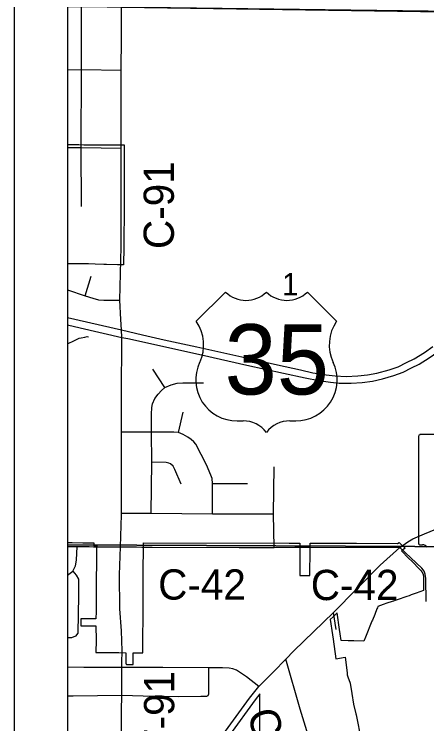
# Model space of a CAD drawing. Extents: x 0 to 34, y 0 to 22.
# Drawn here: x 2 to 2.775, y 16.149 to 17.481 of the extents above; entities that cross this region are included whole.
import ezdxf

# ---------------------------------------------------------------- set-up
doc = ezdxf.new("R2010")
doc.units = 0
for name, color, linetype in [('Default', 7, 'Continuous'), ('GM_X_City_Street', 7, 'Continuous'), ('GM_X_County_Road', 7, 'Continuous'), ('GM_X_County_Road_Text', 7, 'Continuous'), ('GM_X_Minor_River', 7, 'Continuous'), ('GM_X_Section_Text', 7, 'Continuous'), ('GM_X_State_Route', 7, 'Continuous'), ('GM_X_State_Shield', 7, 'Continuous'), ('GM_X_Township_Road', 7, 'Continuous'), ('GM_X_Township_Road_Text', 7, 'Continuous'), ('GM_X_US_Location', 7, 'Continuous'), ('GM_X_US_Route', 7, 'Continuous'), ('GM_X_US_Shield', 7, 'Continuous'), ('SH_Data', 7, 'Continuous')]:
    doc.layers.add(name, color=color, linetype=linetype)

msp = doc.modelspace()

# ---------------------------------------------------------------- linework, layer by layer
at = {"layer": 'Default'}
for points in [[(2.1, 17.4954), (2.1, 16.4848), (3.0135, 16.4807), (3.0196, 17.4831)], [(2.1, 16.4848), (2.1, 15.4427), (3.0163, 15.4353), (3.0168, 15.4789), (3.0135, 16.4807)]]:
    msp.add_lwpolyline(points, close=True, dxfattribs=at)
at = {"layer": 'GM_X_City_Street'}
for p, q in [((2.1335, 16.9523), (2.1447, 16.9889)), ((2.283, 16.78), (2.2602, 16.8145)), ((2.3084, 16.6957), (2.3175, 16.7341)), ((2.3722, 16.5999), (2.4381, 16.5998)), ((2.6045, 16.3261), (2.5999, 16.3579))]:
    msp.add_line(p, q, dxfattribs=at)
for points in [[(2.126, 17.2305), (2.1263, 17.3766), (2.1264, 17.4939)], [(2.1, 17.3765), (2.1263, 17.3766), (2.2007, 17.3758)], [(2.1, 16.9636), (2.1335, 16.9523), (2.148, 16.9475), (2.1585, 16.9449), (2.1682, 16.9438), (2.1982, 16.9438)], [(2.2574, 16.5444), (2.2585, 16.6399), (2.2579, 16.6963), (2.2576, 16.7301), (2.2584, 16.7424), (2.2598, 16.7492), (2.2642, 16.7593), (2.2704, 16.7675), (2.2767, 16.7744), (2.283, 16.78), (2.295, 16.7851), (2.3063, 16.7882), (2.317, 16.7888), (2.3552, 16.7886)], [(2.3722, 16.5433), (2.3722, 16.5999), (2.3717, 16.6094), (2.3694, 16.6156), (2.361, 16.6352), (2.3414, 16.6739), (2.3375, 16.6784), (2.3325, 16.6828), (2.3263, 16.6868), (2.3173, 16.6918), (2.3084, 16.6957), (2.3, 16.6963), (2.2579, 16.6963), (2.2017, 16.6961)], [(2.3138, 16.5988), (2.3017, 16.626), (2.2984, 16.6325), (2.2938, 16.6366), (2.2905, 16.638), (2.2856, 16.6396), (2.2585, 16.6399)], [(2.4882, 16.48), (2.4871, 16.5427), (2.4882, 16.6313)], [(2.2015, 16.5444), (2.2574, 16.5444), (2.3722, 16.5433), (2.4871, 16.5427)], [(2.7739, 16.3787), (2.7728, 16.4216), (2.772, 16.4295), (2.7702, 16.4351), (2.7657, 16.4411), (2.7241, 16.4797)]]:
    msp.add_lwpolyline(points, dxfattribs=at)
at = {"layer": 'GM_X_County_Road'}
for p, q in [((2.1999, 16.4809), (2.201, 16.5209)), ((2.556, 16.4802), (2.7241, 16.4797))]:
    msp.add_line(p, q, dxfattribs=at)
for points in [[(2.2008, 17.3809), (2.2014, 17.4312), (2.2017, 17.4929), (2.2017, 17.5019)], [(2.2006, 17.2295), (2.2011, 17.2643), (2.2007, 17.3758), (2.2008, 17.3809)], [(2.2011, 17.0443), (2.2012, 17.0502), (2.2006, 17.2295)], [(2.2005, 16.9078), (2.1982, 16.9438), (2.2011, 17.0443)], [(2.202, 16.8638), (2.202, 16.8739), (2.2017, 16.8884), (2.2005, 16.9078)], [(2.2016, 16.5816), (2.2017, 16.6961), (2.2017, 16.7751), (2.202, 16.8638)], [(2.201, 16.5209), (2.2015, 16.5409), (2.2015, 16.5444), (2.2016, 16.5816)], [(2.1, 16.4815), (2.1181, 16.4815), (2.121, 16.4815), (2.1285, 16.4814)], [(2.1285, 16.4814), (2.1317, 16.4814), (2.1406, 16.4814), (2.1489, 16.4813)], [(2.1489, 16.4813), (2.1549, 16.4813), (2.159, 16.4812)], [(2.159, 16.4812), (2.1999, 16.4809), (2.2295, 16.4808), (2.2394, 16.4807)], [(2.2394, 16.4807), (2.2591, 16.4805), (2.4222, 16.4797), (2.4777, 16.4799), (2.4863, 16.48)], [(2.4863, 16.48), (2.4882, 16.48), (2.5273, 16.4802), (2.5362, 16.4802)], [(2.5362, 16.4802), (2.5372, 16.4802), (2.5471, 16.4802), (2.556, 16.4802)], [(2.5732, 16.0595), (2.5729, 16.0605), (2.5369, 16.1764), (2.5102, 16.27)]]:
    msp.add_lwpolyline(points, dxfattribs=at)
at = {"layer": 'GM_X_Minor_River'}
msp.add_lwpolyline([(2.1, 16.8618), (2.1038, 16.8637), (2.1096, 16.8666), (2.122, 16.8724), (2.1258, 16.8735), (2.1327, 16.8748), (2.1369, 16.8755), (2.1396, 16.8754)], dxfattribs=at)
at = {"layer": 'GM_X_State_Route'}
for points in [[(2.1, 17.7063), (2.1, 17.2361), (2.1079, 17.236), (2.1211, 17.2359), (2.1306, 17.2358), (2.1614, 17.2356), (2.1644, 17.2355), (2.1952, 17.2353), (2.2066, 17.2352), (2.2063, 17.1184), (2.2063, 17.1106), (2.2062, 17.0554), (2.2062, 17.0517), (2.2061, 17.0489), (2.206, 17.0432), (2.2055, 17.0106), (2.2055, 17.0104), (2.196, 17.0106), (2.194, 17.0106), (2.1736, 17.0111), (2.1686, 17.0112), (2.1522, 17.0116), (2.1396, 17.0119), (2.1252, 17.0122), (2.1204, 17.0123), (2.1156, 17.0123), (2.1017, 17.0124), (2.1, 17.0124), (2.1, 16.4889), (2.1088, 16.4889), (2.1287, 16.4888), (2.1494, 16.4888), (2.1494, 16.4831), (2.1549, 16.4831), (2.1548, 16.4775), (2.1548, 16.4737), (2.1544, 16.4411), (2.1541, 16.4292), (2.1539, 16.4238), (2.1539, 16.4222), (2.154, 16.4125), (2.1539, 16.3992), (2.1538, 16.3859), (2.1537, 16.3727), (2.1537, 16.3594), (2.1536, 16.3462), (2.1252, 16.3461), (2.1251, 16.3328), (2.1535, 16.3329), (2.1539, 16.3056), (2.1533, 16.2829), (2.1579, 16.2828), (2.17, 16.2827), (2.1821, 16.2826), (2.1963, 16.2825), (2.2095, 16.2824), (2.2095, 16.2629), (2.2095, 16.2628), (2.2095, 16.2627), (2.2095, 16.2625), (2.2095, 16.2623), (2.2095, 16.2623), (2.2096, 16.2622), (2.2096, 16.262), (2.2097, 16.2619), (2.2097, 16.2618), (2.2098, 16.2617), (2.2098, 16.2616), (2.2099, 16.2615), (2.21, 16.2613), (2.2101, 16.2612), (2.2102, 16.2611), (2.2103, 16.261), (2.2104, 16.2609), (2.2105, 16.2608), (2.2106, 16.2607), (2.2108, 16.2606), (2.2109, 16.2605), (2.211, 16.2604), (2.2111, 16.2604), (2.2112, 16.2604), (2.2114, 16.2603), (2.2114, 16.2603), (2.2115, 16.2603), (2.2117, 16.2602), (2.2119, 16.2602), (2.212, 16.2602), (2.2121, 16.2602), (2.2123, 16.2602), (2.2236, 16.2601), (2.2237, 16.2823), (2.2359, 16.2823), (2.2413, 16.2823), (2.2416, 16.3012), (2.2418, 16.3201), (2.242, 16.3391), (2.2422, 16.3502), (2.2422, 16.358), (2.2421, 16.3769), (2.2422, 16.3959), (2.2424, 16.4167), (2.2425, 16.4377), (2.2428, 16.4771), (2.2429, 16.4886), (2.5162, 16.4882), (2.5238, 16.4882), (2.5367, 16.4881), (2.5366, 16.4758), (2.5362, 16.4271), (2.547, 16.4272), (2.5555, 16.4273), (2.556, 16.4758), (2.5561, 16.4881), (2.5754, 16.4881), (2.5787, 16.488), (2.636, 16.4878), (2.6431, 16.4877), (2.7198, 16.4871), (2.7231, 16.4895), (2.734, 16.4786), (2.7271, 16.4734), (2.7404, 16.4601), (2.7472, 16.4533), (2.7611, 16.4394), (2.763, 16.4375), (2.7634, 16.4371), (2.7636, 16.4368), (2.7639, 16.4365), (2.7641, 16.4362), (2.7643, 16.4359), (2.7646, 16.4356), (2.7648, 16.4353), (2.765, 16.435), (2.7652, 16.4347), (2.7655, 16.4343), (2.7657, 16.434), (2.7659, 16.4337), (2.7661, 16.4333), (2.7662, 16.433), (2.7664, 16.4327), (2.7666, 16.4323), (2.7668, 16.432), (2.7669, 16.4316), (2.7671, 16.4313), (2.7672, 16.4309), (2.7674, 16.4306), (2.7675, 16.4302), (2.7677, 16.4298), (2.7678, 16.4295), (2.7679, 16.4291), (2.768, 16.4287), (2.7681, 16.4284), (2.7682, 16.428), (2.7683, 16.4276), (2.7684, 16.4273), (2.7685, 16.4269), (2.7686, 16.4265), (2.7686, 16.4261), (2.7687, 16.4257), (2.7687, 16.4254), (2.7688, 16.425), (2.7688, 16.4246), (2.7689, 16.4242), (2.7689, 16.4241), (2.7689, 16.4238), (2.7689, 16.4234), (2.7689, 16.4231), (2.7689, 16.4227), (2.7689, 16.4223), (2.7689, 16.4219), (2.7689, 16.4215), (2.7689, 16.4211), (2.7689, 16.4161), (2.7689, 16.4065), (2.7689, 16.3989), (2.7549, 16.394), (2.7456, 16.3908), (2.7441, 16.3903), (2.7428, 16.3899), (2.7415, 16.3894), (2.7372, 16.3879), (2.7195, 16.3818), (2.7153, 16.3804), (2.7123, 16.3794), (2.7116, 16.3791), (2.71, 16.3786), (2.7078, 16.3778), (2.7018, 16.3757), (2.6998, 16.3751), (2.6928, 16.3726), (2.6831, 16.3693), (2.682, 16.3666), (2.6812, 16.3646), (2.677, 16.3542), (2.6727, 16.3437), (2.6718, 16.3415), (2.6597, 16.3118), (2.6566, 16.3043), (2.6379, 16.3047), (2.6269, 16.3049), (2.6139, 16.3053), (2.6123, 16.3177), (2.6122, 16.3179), (2.6111, 16.3259), (2.6066, 16.3574), (2.599, 16.3499), (2.5936, 16.3446), (2.5977, 16.3156), (2.5988, 16.3078), (2.6039, 16.2709), (2.6214, 16.2739), (2.625, 16.2445), (2.6255, 16.2406), (2.6268, 16.237), (2.6308, 16.2254), (2.634, 16.2057), (2.6375, 16.1856), (2.6415, 16.1674), (2.6419, 16.1655), (2.6452, 16.1499), (2.6486, 16.1341)], [(2.7241, 16.4797), (2.7391, 16.4902), (2.7488, 16.4958), (2.7704, 16.5056), (2.8022, 16.5188), (2.8401, 16.5344), (2.8948, 16.5568), (2.9692, 16.5869), (2.9718, 16.588)], [(2.5102, 16.27), (2.525, 16.2858), (2.5999, 16.3579), (2.6873, 16.4465), (2.7241, 16.4797)], [(2.3334, 16.0479), (2.3508, 16.0723), (2.3775, 16.1087), (2.3919, 16.1283), (2.4166, 16.1625), (2.4419, 16.1972), (2.4592, 16.2187), (2.4869, 16.2465), (2.5102, 16.27)], [(2.4612, 16.1256), (2.4614, 16.1634), (2.4615, 16.1793), (2.4616, 16.2052), (2.4523, 16.1939), (2.4043, 16.1276)]]:
    msp.add_lwpolyline(points, dxfattribs=at)
at = {"layer": 'GM_X_State_Shield'}
for p, q in [((2.7592, 16.6881), (2.7592, 16.488)), ((2.839, 16.6916), (2.7618, 16.6916))]:
    msp.add_line(p, q, dxfattribs=at)
for centre, radius, start, end in [((2.7622, 16.6885), 0.00305, 98.1301, 188.1301), ((2.7622, 16.4876), 0.00308, 171.9584, 258.3066), ((2.7627, 16.508), 0.0235, 267.339, 280.6039), ((2.7675, 16.4764), 0.00848, 29.7484, 93.2717)]:
    msp.add_arc(centre, radius, start, end, dxfattribs=at)
at = {"layer": 'GM_X_Township_Road'}
for p, q in [((2.1265, 17.1196), (2.126, 17.2305)), ((2.1076, 16.3102), (2.1, 16.3102))]:
    msp.add_line(p, q, dxfattribs=at)
for points in [[(3.0233, 15.5768), (3.0198, 16.3586), (3.018, 16.4163), (3.0163, 16.6061), (3.0141, 16.8752), (3.0141, 16.8793), (3.0149, 17.0299), (3.0151, 17.0528), (3.0151, 17.0635), (3.0153, 17.0702), (3.0204, 17.2302), (3.021, 17.2383), (3.0221, 17.3705), (3.0222, 17.3748), (3.0222, 17.4806), (3.0222, 17.4813), (2.2015, 17.4935), (2.1476, 17.4943), (2.1261, 17.4945), (2.1, 17.494), (2.1, 14.1)], [(2.1, 17.2305), (2.126, 17.2305), (2.2006, 17.2295)], [(2.1, 16.4277), (2.1102, 16.4356), (2.115, 16.4457), (2.1172, 16.4558), (2.1181, 16.4815)], [(2.203, 16.2857), (2.2017, 16.3232), (2.1982, 16.3648), (2.1978, 16.4286), (2.1999, 16.4809)], [(2.1102, 16.4356), (2.1165, 16.4276), (2.1208, 16.4204), (2.1208, 16.3896), (2.1194, 16.3191), (2.1153, 16.3131), (2.1076, 16.3102)], [(2.2023, 16.2649), (2.203, 16.2847), (2.203, 16.2857)], [(2.2039, 16.0584), (2.2024, 16.0713), (2.202, 16.0877), (2.202, 16.0967), (2.2013, 16.1452), (2.2018, 16.1738), (2.2021, 16.202), (2.2019, 16.2238), (2.2019, 16.2544), (2.2023, 16.2649)], [(2.4592, 16.2187), (2.4364, 16.2372), (2.427, 16.2435), (2.4173, 16.2495), (2.4104, 16.2522), (2.4035, 16.2533), (2.3909, 16.254), (2.3652, 16.254), (2.2791, 16.2547), (2.2019, 16.2544), (2.1306, 16.2546), (2.1, 16.2551)], [(2.3652, 16.254), (2.3649, 16.2117), (2.3646, 16.2046), (2.3637, 16.2014), (2.3609, 16.2001), (2.3503, 16.2004), (2.308, 16.1997), (2.2625, 16.2001), (2.2021, 16.202), (2.111, 16.2009), (2.1, 16.2009)]]:
    msp.add_lwpolyline(points, dxfattribs=at)
at = {"layer": 'GM_X_US_Route'}
for p, q in [((2.1, 16.9117), (2.2017, 16.8884)), ((2.1, 16.8974), (2.1242, 16.8918)), ((2.1242, 16.8918), (2.202, 16.8739))]:
    msp.add_line(p, q, dxfattribs=at)
for points in [[(2.202, 16.8739), (2.2133, 16.8718), (2.3519, 16.8412), (2.4371, 16.8223), (2.5059, 16.8068), (2.5465, 16.7983), (2.5722, 16.7932), (2.5937, 16.7899), (2.6104, 16.7884), (2.6327, 16.7884), (2.6536, 16.7897), (2.6727, 16.792), (2.6914, 16.7966), (2.7128, 16.8025), (2.7303, 16.8089), (2.7461, 16.8168), (2.7602, 16.8239), (2.7796, 16.8359), (2.7954, 16.8472), (2.8124, 16.8611), (2.8731, 16.9178), (2.906, 16.9486), (2.937, 16.9785)], [(2.2017, 16.8884), (2.2408, 16.879), (2.2819, 16.8698), (2.3431, 16.8566), (2.4276, 16.8374), (2.4944, 16.8226), (2.5374, 16.813), (2.5609, 16.8079), (2.5856, 16.804), (2.603, 16.8017), (2.6236, 16.8009), (2.6453, 16.8018), (2.6637, 16.8038), (2.6813, 16.8073), (2.7043, 16.8135), (2.7211, 16.8189), (2.7369, 16.8268), (2.7511, 16.8339), (2.7705, 16.8459), (2.7862, 16.8572)]]:
    msp.add_lwpolyline(points, dxfattribs=at)
at = {"layer": 'GM_X_US_Shield'}
for p, q in [((2.3968, 16.9592), (2.3419, 16.9043)), ((2.6055, 16.9043), (2.5506, 16.9592)), ((2.4188, 16.7175), (2.4297, 16.7175)), ((2.5176, 16.7175), (2.5286, 16.7175))]:
    msp.add_line(p, q, dxfattribs=at)
for centre, radius, start, end in [((2.4352, 16.9985), 0.0549, 225.573, 314.427), ((2.5121, 16.9985), 0.0549, 225.573, 314.427), ((2.2789, 16.8602), 0.0769, 334.5471, 35.0009), ((2.6685, 16.8602), 0.0769, 144.9991, 205.4529), ((2.4179, 16.7944), 0.0769, 154.8319, 270.6383), ((2.5295, 16.7944), 0.0769, 269.3617, 25.1681), ((2.4297, 16.6626), 0.0549, 36.8699, 90), ((2.5176, 16.6626), 0.0549, 90, 143.1301)]:
    msp.add_arc(centre, radius, start, end, dxfattribs=at)
at = {"layer": 'SH_Data'}
for p, q in [((2, 21), (2, 14)), ((2.1, 20.9), (2.1, 14.1))]:
    msp.add_line(p, q, dxfattribs=at)

# ---------------------------------------------------------------- texts
at = {"layer": 'GM_X_County_Road_Text'}
for s, height, rotation, p in [('C-91', 0.05682, 90, (2.2999, 17.0399)), ('C-42', 0.05682, 0, (2.2704, 16.382)), ('C-42', 0.05682, 0, (2.557, 16.3811)), ('C', 0.0568, 286.7142, (2.4369, 16.1685))]:
    msp.add_text(s, height=height, rotation=rotation, dxfattribs=at).set_placement(p)
at = {"layer": 'GM_X_Section_Text'}
msp.add_text('1', height=0.0419, rotation=0, dxfattribs=at).set_placement((2.5029, 16.9532))
at = {"layer": 'GM_X_Township_Road_Text'}
msp.add_text('T-91', height=0.05682, rotation=89.9973, dxfattribs=at).set_placement((2.3006, 16.092))
at = {"layer": 'GM_X_US_Location'}
for s in ['0', '/']:
    msp.add_text(s, height=0.000189, dxfattribs=at).set_placement((2.4736, 16.8318))
msp.add_text('35', height=0.000189, rotation=0, dxfattribs=at).set_placement((2.4345, 16.7926))
at = {"layer": 'GM_X_US_Shield'}
msp.add_text('35', height=0.13184, dxfattribs=at).set_placement((2.3951, 16.767))

doc.saveas('drawing.dxf')
